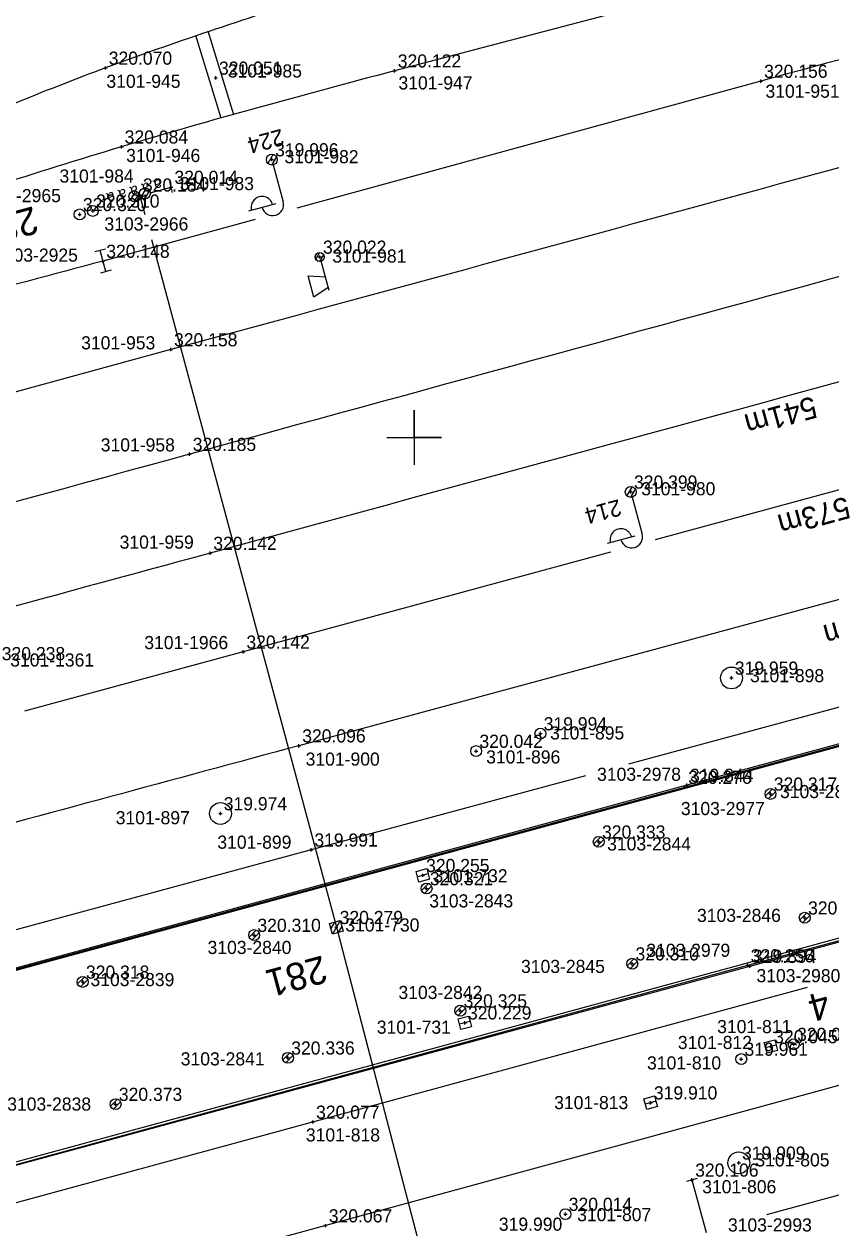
# Model space of a CAD drawing. Extents: x -821875 to -821475, y -1070280 to -1069975.
# Drawn here: x -821717.8 to -821680.9, y -1070236.2 to -1070181.1 of the extents above; entities that cross this region are included whole.
import ezdxf

# ---------------------------------------------------------------- set-up
doc = ezdxf.new("R2010")
doc.units = 0
for name, color, linetype in [('Vrstva 1', 7, 'Continuous'), ('Vrstva 11', 7, 'Continuous'), ('Vrstva 14', 7, 'Continuous'), ('Vrstva 25', 7, 'Continuous'), ('Vrstva 28', 7, 'Continuous'), ('Vrstva 3', 7, 'Continuous'), ('Vrstva 33', 7, 'Continuous'), ('Vrstva 36', 7, 'Continuous'), ('Vrstva 41', 7, 'Continuous'), ('Vrstva 43', 7, 'Continuous'), ('Vrstva 6', 7, 'Continuous'), ('Vrstva 60', 7, 'Continuous'), ('Vrstva 61', 7, 'Continuous'), ('Vrstva 7', 7, 'Continuous')]:
    doc.layers.add(name, color=color, linetype=linetype)

# ---------------------------------------------------------------- blocks, each defined once
blk = doc.blocks.new('BOD')
at = {"layer": 'Vrstva 3'}
for p, q in [((-0.15, 0), (0.15, 0)), ((0, -0.15), (0, 0.15))]:
    blk.add_line(p, q, dxfattribs=at)

msp = doc.modelspace()

# ---------------------------------------------------------------- linework, layer by layer
at = {"layer": 'Vrstva 1'}
for p, q in [((-821668.007, -1070204.011), (-821705.268, -1070214.096)), ((-821668.941, -1070209.195), (-821690.189, -1070214.936)), ((-821692.166, -1070215.471), (-821704.713, -1070218.861)), ((-821704.713, -1070218.861), (-821732.499, -1070226.383))]:
    msp.add_line(p, q, dxfattribs=at)
for points in [[(-821689.454, -1070180.207), (-821700.898, -1070183.216)], [(-821684.141, -1070183.689), (-821705.358, -1070189.495)], [(-821707.267, -1070190.018), (-821714.233, -1070191.924)], [(-821711.133, -1070195.974), (-821736.713, -1070202.967)], [(-821701.25, -1070200), (-821700, -1070200), (-821700, -1070198.75), (-821700, -1070200), (-821698.75, -1070200), (-821700, -1070200), (-821700, -1070201.25)], [(-821670.833, -1070199.746), (-821688.982, -1070204.681)], [(-821691.017, -1070205.235), (-821717.82, -1070212.523)], [(-821682.027, -1070225.161), (-821721.87, -1070236.004)], [(-821667.464, -1070226.079), (-821669.621, -1070226.661), (-821739.032, -1070245.599)], [(-821666.751, -1070230.896), (-821668.47, -1070231.368), (-821683.884, -1070235.554)]]:
    msp.add_lwpolyline(points, dxfattribs=at)
for points in [[(-821500, -1070134.157), (-821525.227, -1070140.424), (-821545.665, -1070145.962), (-821584.89, -1070156.649), (-821608.863, -1070163.173), (-821645.742, -1070173.228), (-821684.141, -1070183.689)], [(-821500, -1070139.002), (-821505.719, -1070140.359), (-821526.796, -1070145.75), (-821547.362, -1070151.333), (-821583.687, -1070161.245), (-821611.332, -1070168.765), (-821648.899, -1070179.006), (-821680.4, -1070187.609), (-821711.133, -1070195.974)], [(-821500, -1070143.947), (-821500.602, -1070144.082), (-821526.98, -1070150.62), (-821544.477, -1070155.432), (-821558.026, -1070159.151), (-821579.135, -1070164.951), (-821610.376, -1070173.463), (-821647.463, -1070183.595), (-821678.921, -1070192.191), (-821710.276, -1070200.761)], [(-821679.285, -1070162.663), (-821695.528, -1070167.095), (-821716.799, -1070174.043), (-821730.799, -1070179.932), (-821744.379, -1070186.736), (-821755.356, -1070192.851), (-821764.427, -1070198.469)], [(-821677.113, -1070166.912), (-821699.427, -1070173.07), (-821715.575, -1070178.704), (-821729.749, -1070184.723), (-821746.361, -1070192.156), (-821759.601, -1070198.262)], [(-821682.977, -1070173.434), (-821704.603, -1070179.855), (-821714.119, -1070183.088), (-821722.706, -1070186.589), (-821730.813, -1070190.332)], [(-821700.898, -1070183.216), (-821713.391, -1070186.695), (-821719.286, -1070188.528)], [(-821714.233, -1070191.924), (-821727.927, -1070195.569), (-821741.295, -1070199.32), (-821748.807, -1070201.766)], [(-821672.303, -1070195.209), (-821676.947, -1070196.473), (-821709.336, -1070205.287)], [(-821710.276, -1070200.761), (-821741.264, -1070209.238), (-821760.235, -1070214.402), (-821776.338, -1070219.041), (-821794.464, -1070225.772), (-821811.866, -1070233.595), (-821823.5, -1070239.204)], [(-821709.336, -1070205.287), (-821731.872, -1070211.395), (-821757.763, -1070218.461), (-821767.367, -1070221.229)], [(-821705.268, -1070214.096), (-821739.917, -1070223.49), (-821760.504, -1070229.155), (-821769.875, -1070231.779)]]:
    msp.add_spline(points, degree=3, dxfattribs=at)
at = {"layer": 'Vrstva 11'}
for p, q in [((-821712.747, -1070188.713), (-821712.981, -1070189.123)), ((-821712.59, -1070188.817), (-821712.812, -1070189.205)), ((-821712.555, -1070188.891), (-821712.315, -1070189.786)), ((-821712.262, -1070188.583), (-821712.498, -1070188.993)), ((-821712.106, -1070188.688), (-821712.328, -1070189.074)), ((-821712.008, -1070190.93), (-821703.558, -1070222.406)), ((-821703.636, -1070222.168), (-821703.803, -1070222.458)), ((-821703.382, -1070222.101), (-821703.733, -1070222.712)), ((-821703.558, -1070222.406), (-821698.291, -1070242.616)), ((-821703.313, -1070222.357), (-821703.477, -1070222.643))]:
    msp.add_line(p, q, dxfattribs=at)
msp.add_lwpolyline([(-821703.252, -1070222.582), (-821703.734, -1070222.712), (-821703.864, -1070222.23), (-821703.382, -1070222.1)], close=True, dxfattribs=at)
msp.add_lwpolyline([(-821703.252, -1070222.582), (-821703.734, -1070222.712), (-821703.864, -1070222.23), (-821703.382, -1070222.1), (-821703.252, -1070222.582)], dxfattribs=at)
for centre in [(-821712.796, -1070188.956), (-821712.796, -1070188.956), (-821712.314, -1070188.826), (-821712.314, -1070188.826)]:
    msp.add_circle(centre, 0.25, dxfattribs=at)
at = {"layer": 'Vrstva 14'}
for p, q in [((-821664.962, -1070209.896), (-821757.694, -1070235.105)), ((-821687.611, -1070215.993), (-821664.691, -1070209.733)), ((-821664.66, -1070209.694), (-821687.531, -1070215.9)), ((-821687.531, -1070215.9), (-821729.11, -1070227.249)), ((-821729.033, -1070227.268), (-821687.611, -1070215.993)), ((-821768.204, -1070246.736), (-821665.012, -1070218.658)), ((-821664.58, -1070218.678), (-821684.759, -1070224.159)), ((-821684.647, -1070224.184), (-821664.729, -1070218.735)), ((-821684.759, -1070224.159), (-821727.507, -1070235.797)), ((-821727.465, -1070235.8), (-821684.647, -1070224.184))]:
    msp.add_line(p, q, dxfattribs=at)
at = {"layer": 'Vrstva 25'}
for p, q in [((-821706.452, -1070187.039), (-821706.69, -1070187.454)), ((-821706.299, -1070187.148), (-821706.517, -1070187.529)), ((-821706.445, -1070187.522), (-821705.988, -1070189.211)), ((-821706.326, -1070189.303), (-821707.581, -1070189.642)), ((-821690.034, -1070202.241), (-821690.273, -1070202.656)), ((-821689.881, -1070202.35), (-821690.101, -1070202.732)), ((-821690.028, -1070202.725), (-821689.572, -1070204.414)), ((-821689.91, -1070204.505), (-821691.166, -1070204.844)), ((-821694.248, -1070213.543), (-821694.198, -1070213.543)), ((-821697.188, -1070214.344), (-821697.138, -1070214.344)), ((-821682.659, -1070227.755), (-821682.609, -1070227.755)), ((-821685.063, -1070228.433), (-821685.013, -1070228.433)), ((-821693.104, -1070235.529), (-821693.054, -1070235.529))]:
    msp.add_line(p, q, dxfattribs=at)
for centre in [(-821706.51, -1070187.281), (-821706.51, -1070187.281), (-821690.093, -1070202.483), (-821690.093, -1070202.483), (-821694.223, -1070213.543), (-821697.163, -1070214.344), (-821682.634, -1070227.755), (-821685.038, -1070228.433), (-821693.079, -1070235.529)]:
    msp.add_circle(centre, 0.25, dxfattribs=at)
for centre, start, end in [((-821706.955, -1070189.467), 14.4228, 195.828), ((-821706.471, -1070189.342), 195.1254, 15.1254), ((-821690.54, -1070204.668), 14.3752, 195.7804), ((-821690.056, -1070204.544), 195.0778, 15.0778)]:
    msp.add_arc(centre, 0.5, start, end, dxfattribs=at)
at = {"layer": 'Vrstva 28'}
for p, q in [((-821715.323, -1070189.787), (-821715.273, -1070189.787)), ((-821714.722, -1070189.627), (-821714.672, -1070189.627))]:
    msp.add_line(p, q, dxfattribs=at)
for centre in [(-821714.697, -1070189.627), (-821715.298, -1070189.787)]:
    msp.add_circle(centre, 0.25, dxfattribs=at)
at = {"layer": 'Vrstva 3'}
for p, q in [((-821714.12, -1070191.377), (-821714.603, -1070191.505)), ((-821714.105, -1070192.407), (-821714.361, -1070191.441)), ((-821713.863, -1070192.343), (-821714.346, -1070192.471))]:
    msp.add_line(p, q, dxfattribs=at)
at = {"layer": 'Vrstva 33'}
for p, q in [((-821704.324, -1070191.537), (-821704.494, -1070191.833)), ((-821704.148, -1070191.633), (-821704.322, -1070191.935)), ((-821703.889, -1070193.275), (-821704.255, -1070191.926)), ((-821704.587, -1070193.568), (-821704.848, -1070192.602)), ((-821704.848, -1070192.602), (-821704.059, -1070192.648)), ((-821703.928, -1070193.131), (-821704.587, -1070193.568))]:
    msp.add_line(p, q, dxfattribs=at)
for radius in [0.201, 0.2]:
    msp.add_circle((-821704.319, -1070191.736), radius, dxfattribs=at)
at = {"layer": 'Vrstva 36'}
for p, q in [((-821683.93, -1070216.393), (-821683.606, -1070216.07)), ((-821683.8, -1070216.528), (-821683.472, -1070216.2)), ((-821691.786, -1070218.585), (-821691.464, -1070218.262)), ((-821691.656, -1070218.72), (-821691.329, -1070218.392)), ((-821699.662, -1070220.723), (-821699.338, -1070220.4)), ((-821699.532, -1070220.858), (-821699.204, -1070220.53)), ((-821682.362, -1070222.061), (-821682.038, -1070221.738)), ((-821682.232, -1070222.196), (-821681.904, -1070221.868)), ((-821707.548, -1070222.855), (-821707.226, -1070222.532)), ((-821707.418, -1070222.99), (-821707.091, -1070222.662)), ((-821690.254, -1070224.163), (-821689.932, -1070223.84)), ((-821690.124, -1070224.298), (-821689.797, -1070223.97)), ((-821715.392, -1070224.997), (-821715.068, -1070224.674)), ((-821715.262, -1070225.132), (-821714.934, -1070224.804)), ((-821698.118, -1070226.312), (-821697.794, -1070225.989)), ((-821697.988, -1070226.447), (-821697.66, -1070226.12)), ((-821706.002, -1070228.469), (-821705.678, -1070228.146)), ((-821705.872, -1070228.604), (-821705.544, -1070228.276)), ((-821713.886, -1070230.59), (-821713.564, -1070230.267)), ((-821713.756, -1070230.725), (-821713.429, -1070230.398))]:
    msp.add_line(p, q, dxfattribs=at)
for centre in [(-821683.699, -1070216.301), (-821691.556, -1070218.493), (-821699.431, -1070220.631), (-821682.131, -1070221.969), (-821707.318, -1070222.763), (-821690.024, -1070224.071), (-821715.161, -1070224.905), (-821697.887, -1070226.22), (-821705.771, -1070228.377), (-821713.656, -1070230.498)]:
    msp.add_circle(centre, 0.25, dxfattribs=at)
at = {"layer": 'Vrstva 41'}
for p, q in [((-821687.054, -1070233.898), (-821687.536, -1070234.03)), ((-821687.295, -1070233.964), (-821686.637, -1070236.376))]:
    msp.add_line(p, q, dxfattribs=at)
at = {"layer": 'Vrstva 43'}
for points in [[(-821699.362, -1070219.963), (-821699.297, -1070220.204), (-821699.78, -1070220.333), (-821699.909, -1070219.85), (-821699.426, -1070219.721), (-821699.362, -1070219.963), (-821699.844, -1070220.091)], [(-821697.444, -1070226.71), (-821697.381, -1070226.952), (-821697.866, -1070227.077), (-821697.991, -1070226.592), (-821697.506, -1070226.467), (-821697.444, -1070226.71), (-821697.928, -1070226.834)], [(-821683.438, -1070227.796), (-821683.374, -1070228.039), (-821683.859, -1070228.166), (-821683.986, -1070227.681), (-821683.501, -1070227.554), (-821683.438, -1070227.796), (-821683.922, -1070227.924)], [(-821688.942, -1070230.363), (-821688.875, -1070230.604), (-821689.357, -1070230.738), (-821689.491, -1070230.256), (-821689.009, -1070230.122), (-821688.942, -1070230.363), (-821689.424, -1070230.497)]]:
    msp.add_lwpolyline(points, dxfattribs=at)
for centre in [(-821685.482, -1070210.996), (-821708.859, -1070217.202), (-821685.151, -1070233.185)]:
    msp.add_circle(centre, 0.5, dxfattribs=at)
at = {"layer": 'Vrstva 6'}
for p, q in [((-821711.048, -1070188.781), (-821711.178, -1070188.299)), ((-821712.068, -1070188.799), (-821711.113, -1070188.54))]:
    msp.add_line(p, q, dxfattribs=at)
at = {"layer": 'Vrstva 7'}
for p, q in [((-821708.823, -1070185.385), (-821709.992, -1070181.601)), ((-821708.244, -1070185.225), (-821709.424, -1070181.405))]:
    msp.add_line(p, q, dxfattribs=at)

# ---------------------------------------------------------------- block references
at = {"layer": 'Vrstva 60', "xscale": 0.5, "yscale": 0.5}
for p in [(-821714.119, -1070183.088), (-821700.898, -1070183.216), (-821709.077, -1070183.545), (-821684.141, -1070183.689), (-821713.391, -1070186.695), (-821706.51, -1070187.281), (-821712.555, -1070188.891), (-821711.113, -1070188.54), (-821715.298, -1070189.787), (-821714.697, -1070189.627), (-821704.319, -1070191.736), (-821714.233, -1070191.924), (-821711.133, -1070195.974), (-821710.276, -1070200.761), (-821690.093, -1070202.483), (-821709.336, -1070205.287), (-821707.822, -1070209.805), (-821685.482, -1070210.996), (-821694.223, -1070213.543), (-821705.268, -1070214.096), (-821697.163, -1070214.344), (-821687.611, -1070215.993), (-821687.531, -1070215.9), (-821683.699, -1070216.301), (-821708.859, -1070217.202), (-821691.556, -1070218.493), (-821704.713, -1070218.861), (-821699.603, -1070220.027), (-821699.431, -1070220.631), (-821682.131, -1070221.969), (-821703.558, -1070222.406), (-821707.318, -1070222.763), (-821690.024, -1070224.071), (-821684.759, -1070224.159), (-821684.647, -1070224.184), (-821715.161, -1070224.905), (-821697.887, -1070226.22), (-821697.686, -1070226.772), (-821683.68, -1070227.86), (-821682.634, -1070227.755), (-821705.771, -1070228.377), (-821685.038, -1070228.433), (-821713.656, -1070230.498), (-821689.183, -1070230.43), (-821704.635, -1070231.313), (-821685.151, -1070233.185), (-821687.295, -1070233.964), (-821693.079, -1070235.529), (-821704.054, -1070236.056)]:
    msp.add_blockref('BOD', p, dxfattribs=at)

# ---------------------------------------------------------------- texts
at = {"layer": 'Vrstva 1'}
for s, height, rotation, p in [('541m', 1, 195.2312, (-821681.745, -1070198.096)), ('573m', 1, 195.1773, (-821680.225, -1070202.687)), ('162m', 1, 195.241, (-821678.137, -1070207.731)), ('4', 1.25, 195.2599, (-821681.184, -1070225.293))]:
    msp.add_text(s, height=height, rotation=rotation, dxfattribs=at).set_placement(p)
at = {"layer": 'Vrstva 11'}
for s, rotation, p in [('282', 195.1705, (-821717.41, -1070189.403)), ('281', 195.0979, (-821704.189, -1070223.682))]:
    msp.add_text(s, height=1.25, rotation=rotation, dxfattribs=at).set_placement(p)
at = {"layer": 'Vrstva 25'}
for s, rotation, p in [('224', 195.1255, (-821706.074, -1070185.864)), ('214', 195.0779, (-821690.642, -1070202.812))]:
    msp.add_text(s, height=0.75, rotation=rotation, dxfattribs=at).set_placement(p)
at = {"layer": 'Vrstva 6'}
msp.add_text('  a a a a a', height=0.5, rotation=195.1673, dxfattribs=at).set_placement((-821711.244, -1070188.057))
at = {"layer": 'Vrstva 60'}
for s, p in [('3101-985', (-821708.523, -1070183.524)), ('3101-945', (-821714.075, -1070183.995)), ('3101-947', (-821700.717, -1070184.07)), ('3101-951', (-821683.929, -1070184.45)), ('3101-946', (-821713.173, -1070187.392)), ('3101-982', (-821705.932, -1070187.447)), ('3101-984', (-821716.22, -1070188.332)), ('3101-983', (-821710.717, -1070188.677)), ('3103-2965', (-821719.995, -1070189.228)), ('3103-2966', (-821714.166, -1070190.525)), ('3103-2925', (-821719.216, -1070191.95)), ('3101-981', (-821703.744, -1070191.993)), ('3101-953', (-821715.23, -1070195.962)), ('3101-958', (-821714.334, -1070200.632)), ('3101-980', (-821689.613, -1070202.64)), ('3101-959', (-821713.471, -1070205.082)), ('3101-1966', (-821712.343, -1070209.677)), ('3101-1361', (-821718.475, -1070210.473)), ('3101-898', (-821684.637, -1070211.191)), ('3101-895', (-821693.78, -1070213.811)), ('3101-896', (-821696.705, -1070214.91)), ('3101-900', (-821704.963, -1070215.009)), ('3103-2978', (-821691.632, -1070215.703)), ('3103-2847', (-821683.264, -1070216.493)), ('3103-2977', (-821687.798, -1070217.271)), ('3101-897', (-821713.651, -1070217.691)), ('3101-899', (-821709.003, -1070218.809)), ('3103-2844', (-821691.173, -1070218.891)), ('3101-732', (-821699.116, -1070220.347)), ('3103-2843', (-821699.307, -1070221.495)), ('3101-730', (-821703.148, -1070222.597)), ('3103-2846', (-821687.061, -1070222.16)), ('3103-2840', (-821709.449, -1070223.627)), ('3103-2979', (-821689.379, -1070223.755)), ('3103-2845', (-821695.111, -1070224.495)), ('3103-2839', (-821714.804, -1070225.096)), ('3103-2980', (-821684.342, -1070224.919)), ('3103-2842', (-821700.718, -1070225.686)), ('3101-731', (-821701.709, -1070227.274)), ('3101-811', (-821686.139, -1070227.247)), ('3101-812', (-821687.937, -1070227.974)), ('3103-2841', (-821710.676, -1070228.724)), ('3101-810', (-821689.347, -1070228.909)), ('3103-2838', (-821718.613, -1070230.793)), ('3101-813', (-821693.595, -1070230.724)), ('3101-818', (-821704.951, -1070232.204)), ('3101-805', (-821684.39, -1070233.346)), ('3101-806', (-821686.824, -1070234.574)), ('3101-807', (-821692.544, -1070235.851)), ('3103-2993', (-821685.646, -1070236.322))]:
    msp.add_text(s, height=0.6, dxfattribs=at).set_placement(p)
at = {"layer": 'Vrstva 61'}
for s, p in [('320.070', (-821713.969, -1070182.938)), ('320.051', (-821708.927, -1070183.395)), ('320.122', (-821700.748, -1070183.066)), ('320.156', (-821683.991, -1070183.539)), ('320.084', (-821713.241, -1070186.545)), ('319.996', (-821706.36, -1070187.131)), ('320.014', (-821710.963, -1070188.39)), ('320.184', (-821712.405, -1070188.741)), ('320.310', (-821714.547, -1070189.477)), ('320.320', (-821715.148, -1070189.637)), ('320.148', (-821714.083, -1070191.774)), ('320.022', (-821704.169, -1070191.586)), ('320.158', (-821710.983, -1070195.824)), ('320.185', (-821710.126, -1070200.611)), ('320.399', (-821689.943, -1070202.333)), ('320.142', (-821709.186, -1070205.137)), ('320.142', (-821707.672, -1070209.655)), ('320.238', (-821718.862, -1070210.182)), ('319.959', (-821685.332, -1070210.846)), ('319.994', (-821694.073, -1070213.393)), ('320.096', (-821705.118, -1070213.946)), ('320.042', (-821697.013, -1070214.194)), ('320.276', (-821687.461, -1070215.843)), ('319.844', (-821687.381, -1070215.75)), ('320.317', (-821683.549, -1070216.151)), ('319.974', (-821708.709, -1070217.052)), ('319.991', (-821704.563, -1070218.711)), ('320.333', (-821691.406, -1070218.343)), ('320.255', (-821699.453, -1070219.877)), ('320.321', (-821699.281, -1070220.481)), ('320.304', (-821681.981, -1070221.819)), ('320.310', (-821707.168, -1070222.613)), ('320.279', (-821703.408, -1070222.256)), ('320.310', (-821689.874, -1070223.921)), ('320.256', (-821684.609, -1070224.009)), ('319.894', (-821684.497, -1070224.034)), ('320.318', (-821715.011, -1070224.755)), ('320.325', (-821697.737, -1070226.07)), ('320.229', (-821697.536, -1070226.622)), ('320.045', (-821683.53, -1070227.71)), ('320.009', (-821682.484, -1070227.605)), ('320.336', (-821705.621, -1070228.227)), ('319.961', (-821684.888, -1070228.283)), ('319.910', (-821689.033, -1070230.28)), ('320.373', (-821713.506, -1070230.348)), ('320.077', (-821704.485, -1070231.163)), ('319.909', (-821685.001, -1070233.035)), ('320.106', (-821687.145, -1070233.814)), ('320.014', (-821692.929, -1070235.379)), ('320.067', (-821703.904, -1070235.906)), ('319.990', (-821696.124, -1070236.288))]:
    msp.add_text(s, height=0.6, dxfattribs=at).set_placement(p)

doc.saveas('drawing.dxf')
